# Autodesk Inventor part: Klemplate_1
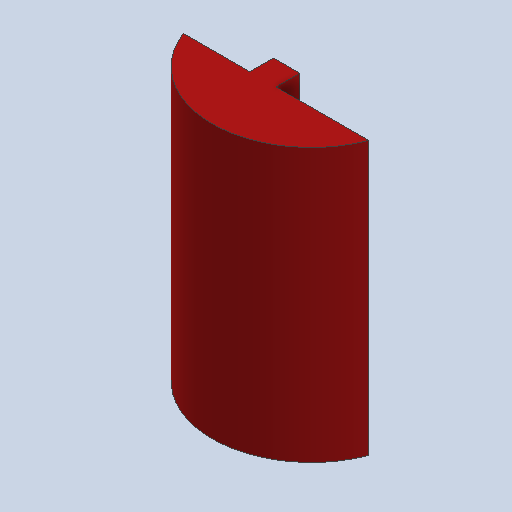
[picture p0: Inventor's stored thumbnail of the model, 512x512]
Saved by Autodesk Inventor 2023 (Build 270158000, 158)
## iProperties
Created: 2025-02
Part Number: Klemplate_1
Material: Generisch
Document SubType Name: Modeling
Designer: MVM1
Density: 1 g/cm^3
Appearance: Vorgabe
Author: MVM1
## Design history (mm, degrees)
derived "Bauteil_Ohne_Scharnier.ipt"
feature "Klemplate_1::Bauteil_Ohne_Scharnier.ipt" dims "d0" = 10
tag "Bezeichnung1"
node "Klemplate_1"
